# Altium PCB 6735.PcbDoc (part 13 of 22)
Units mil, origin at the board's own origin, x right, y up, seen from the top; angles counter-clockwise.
Board outline 2641.73 x 5165.35 mil, 6 copper layers (Top, Inner Layer 2, Inner Layer 3, Inner Layer 4, Inner Layer 5, Bottom), stack 35.7 mil thick; 1011 components, 790 nets, 4118 pads, 9325 vias.
Unrouted connection lines stored in the file: 4610.
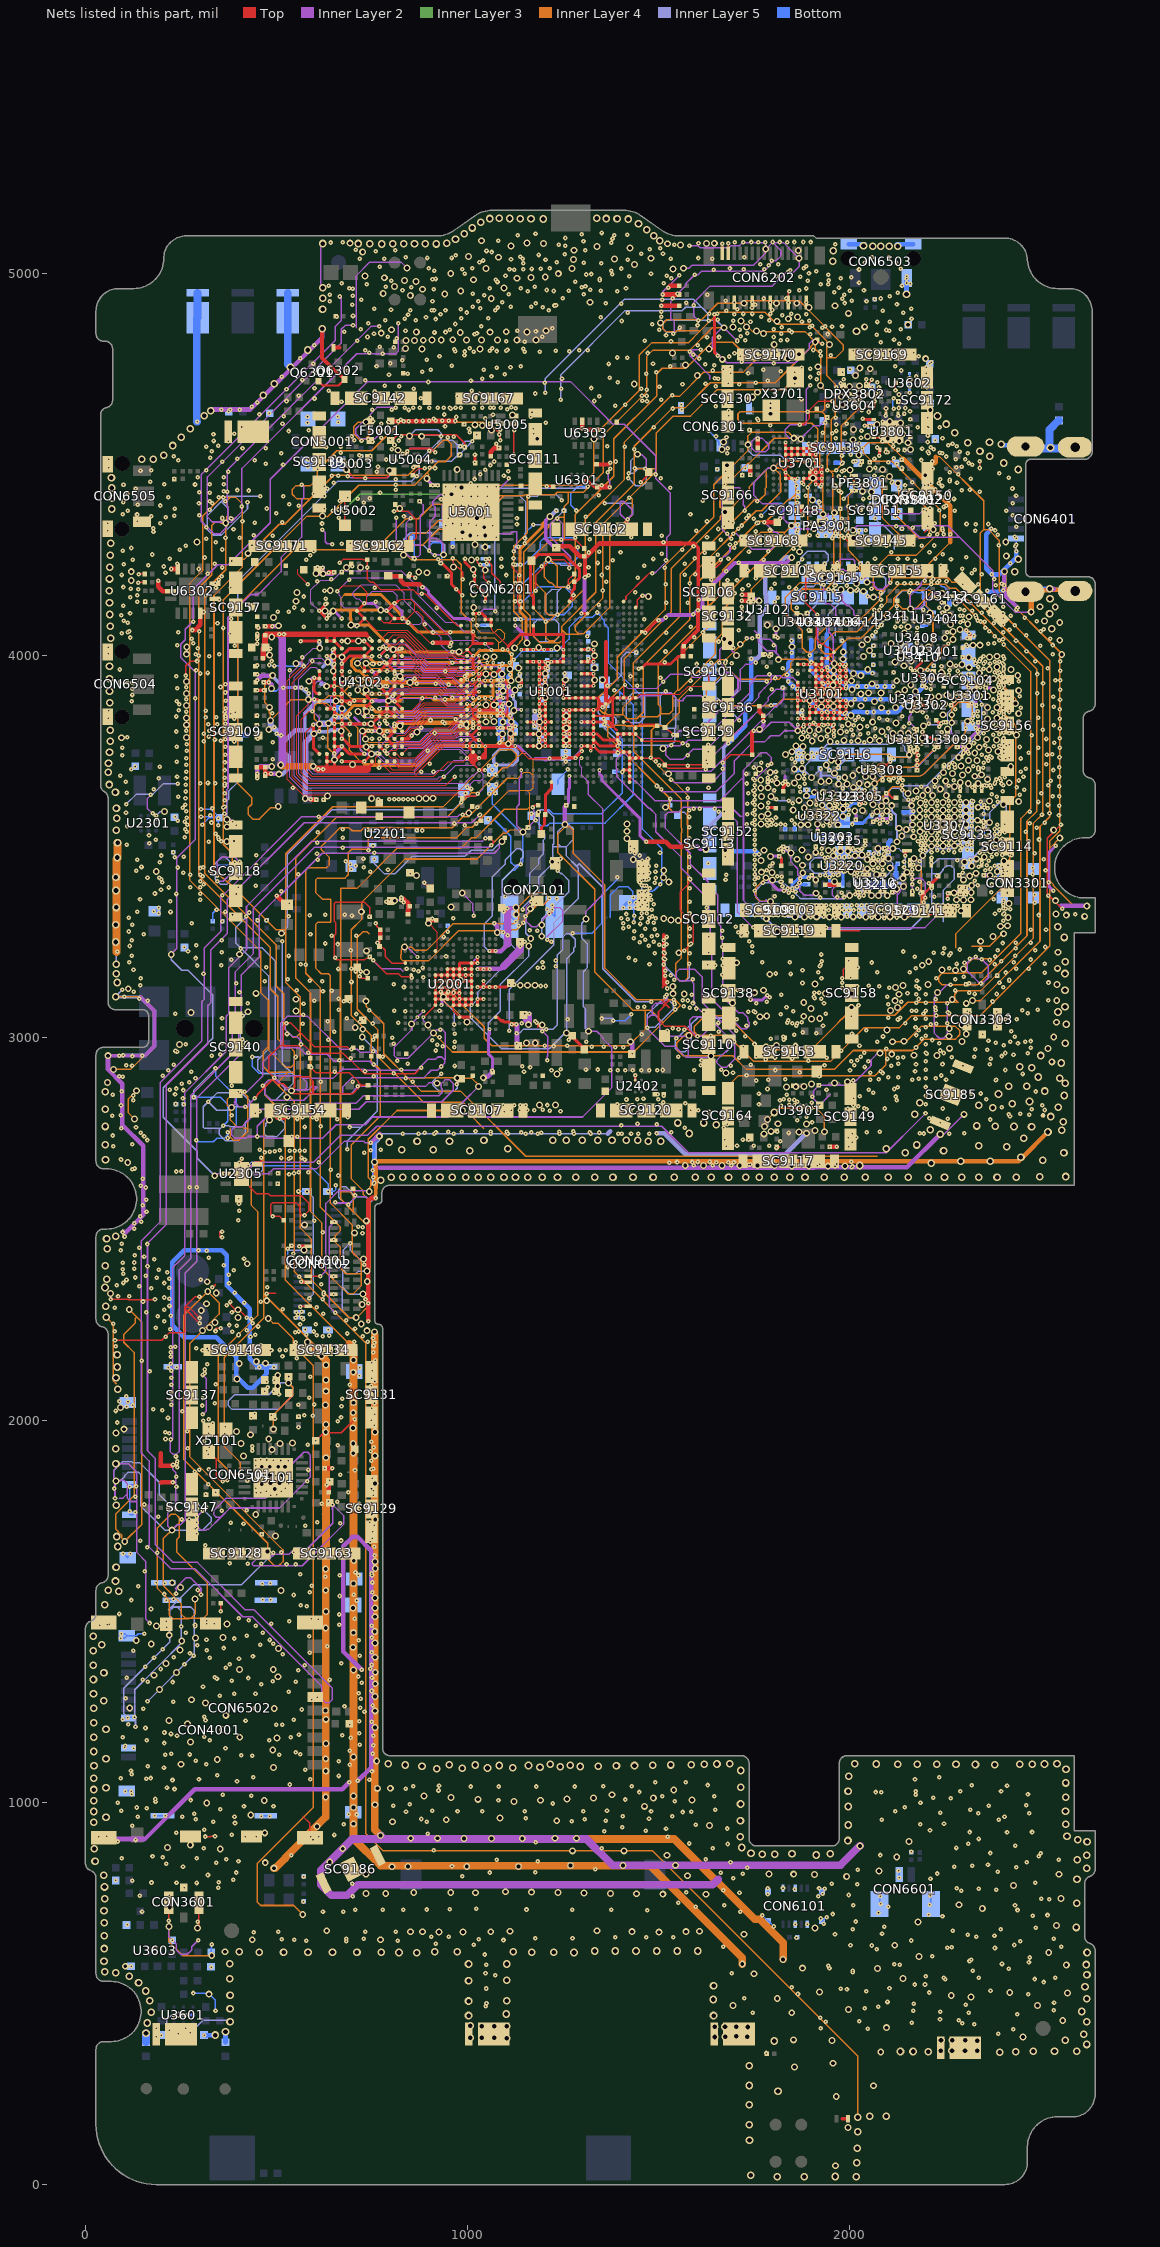
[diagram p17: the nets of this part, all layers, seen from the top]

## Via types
v1: diameter 12, hole 4, Top to Inner Layer 2, 3329 vias
v2: diameter 12, hole 4, Inner Layer 5 to Bottom, 3071 vias
v3: diameter 18, hole 10, Inner Layer 2 to Inner Layer 5, 1928 vias
v4: diameter 10, hole 4, Top to Inner Layer 2, 525 vias
v5: diameter 20, hole 12, Top to Bottom, 472 vias

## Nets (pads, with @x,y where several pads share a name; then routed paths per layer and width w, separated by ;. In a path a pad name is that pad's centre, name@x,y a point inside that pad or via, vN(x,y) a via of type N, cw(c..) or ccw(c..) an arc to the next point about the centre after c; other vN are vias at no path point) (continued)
D_GND: (continued)
  other v3: 1962.31,49.09 1995.15,148.83 1964.31,230.54 2061.64,258.45 1854.82,307.71 1956.17,317.5 2080.63,346.62 1953.05,376.92 1852.87,378.64 2453.27,386.18 2095.55,410.38 2556.8,429.38 246.3,444.09 1847.87,449.5 1996,458.39 1694,468.72 2490.77,468.68 1809.98,487.02 2316.68,490.42 2265.13,494.49 323.3,498.09 2569.01,501.28 2418.42,502.63 1920.87,504.09 2138.96,539.26 1748.85,551.39 2072.49,565.04 1876.41,566.08 104.31,571.09 2566.29,574.53 2181.02,596.24 2520.17,607.09 365.31,609.09 2117.26,626.08 436.42,640.39 771.95,640.49 1723.4,654.7 1500.37,660.31 850.6,661.48 881.79,661.48 924.87,661.07 987.81,660.67 1060.28,661.48 1430.36,661.57 1571.01,661.57 1110.79,662.67 1606.81,662.84 631.31,664.09 1338.21,663.86 293.31,671.09 1908.34,671.27 2540.52,677.63 2178.31,687.13 2346.52,722.4 220.31,725.09 2285.48,731.9 2552.73,748.18 1623.29,759.55 1510.6,759.67 1441.96,760.72 733.89,761.78 785.63,761.78 1373.32,761.78 1020.6,763.36 1304.68,762.83 859.03,764.42 955.66,763.89 1236.03,763.89 1167.39,764.95 1098.75,766 2427.92,782.09 1991.62,805.88 1574.9,807.94 1907.72,811.25 733.89,811.94 1788.47,812.35 1852.98,812.06 2547.3,811.94 2076.14,820.29 801.78,831.59 843.84,832.03 997.62,832.23 1132.59,831.92 1269.37,834.62 1406.49,835 1543.61,835.38 470.41,842.12 639.29,843.77 2122.48,857.23 1521.28,861.56 352.78,878.19 673.22,878.65 214.59,882.23 274.39,888.69 2154.41,897.92 1062.03,905.56 1142.89,905.23 851,906.05 920.76,905.89 990.52,905.73 1228.38,905.89 1284.82,905.89 469.15,920.21 605.79,936.54 1632.56,939.16 701.02,943.96 803.34,949.24 1233.08,951.76 943.86,954.28 1085,959.32 432.52,967.2 701.1,986.7 1462.44,989.57 757.83,993.54 317.22,998.6 1120.92,1002.17 467.89,1004.93 1190.23,1005.32 1587.2,1005.95 1027.03,1007.84 1259.54,1008.47 956.46,1012.25 1328.85,1011.62 1485.75,1011.62 628.83,1014.07 700.88,1016.52 885.89,1016.66 1377.37,1019.81 1539.31,1032.41 763.94,1036.68 797.67,1036.82 628.85,1082.17 491.78,1091.54 250.3,1099.72 761.9,1108.25 344.73,1112.01 628.58,1114.07 700.98,1118.26 489.98,1136.87 629.22,1153.68 274.62,1157.73 501.09,1168.29 403.78,1170.37 358.96,1190.24 757.95,1195.47 267.35,1205.7 218.63,1214.37 629.29,1217.14 367.24,1227.63 757.83,1239.41 628.33,1240 494.08,1245.7 115.73,1247.09 313.99,1259.63 277.62,1268.52 757.71,1277.1 193.56,1295.22 758.07,1310.23 503.84,1328.42 179.07,1332.35 238.11,1339.68 758.19,1340.36 701.04,1346.53 402.65,1347.74 491.35,1347.69 210.96,1363.51 757.83,1379.49 247.34,1398.7 504.95,1402.37 700.34,1405.64 172.13,1413.94 757.35,1416.94 132.74,1423.26 288.07,1430.11 359.51,1431.21 219.11,1437.36 701.19,1443.87 756.75,1446.95 628.82,1456.37 186.1,1460.95 370.56,1466.51 757.29,1485.62 629.37,1499.04 700.21,1508.26 757.6,1508.16 757.6,1534.85 511.66,1554.64 628.64,1554.86 248.46,1562.01 227.06,1574.49 628.55,1610.68 758.27,1612.1 757.44,1630.17 701.91,1632.29 475.91,1656.02 497.06,1697.23 758.19,1740.24 445.56,1753.15 495.31,1820.09 461.31,1832.09 757.67,1834.1 484.31,1835.09 507.31,1835.09 462.31,1856.09 482.31,1856.09 515.31,1856.09 461.31,1878.09 482.31,1878.09 504.31,1878.09 522.31,1878.09 629.12,1901.46 413.67,1906.42 757.24,1906.58 700.5,1913.29 487.66,1922.68 407.17,1938.94 508.8,1938.94 700.64,1939.16 541.45,1940.02 479.7,1950.81 431.75,1961.6 80.31,1966.09 757.37,1968.52 628.64,1968.94 395.48,1970.59 100.92,1976.32 700.37,1979.21 629.14,1988.85 700.58,2019.32 91.35,2032.95 628.39,2039.65 700.92,2045.61 629.08,2075.7 756.46,2075.78 628.99,2104.65 396.6,2107.25 502.95,2117.49 700.81,2125.22 629.04,2144.51 402.29,2147.91 471.4,2148.72 447.01,2153.6 701.01,2157.59 617.78,2167.27 426.79,2180.83 756.53,2231.03 736.7,2234.01 306.33,2234.83 324.45,2242.53 721.67,2251.7 339.32,2255.25 399.42,2268.53 303.06,2286.65 399.42,2288.62 724,2302.25 316.89,2304.44 474.29,2312.55 342.23,2332.72 318.49,2362.04 423.31,2409.05 704.28,2490.05 572.81,2510.97 1892.32,2664.2 1942.72,2664.44 1847.75,2665.28 1987.05,2664.99 1569.14,2666.29 1617.38,2666.36 1665.62,2666.43 1711.93,2666.4 1758.25,2666.38 1803.18,2666.35 110.49,2673.65 756.36,2675.06 1775.12,2749.02 1866.62,2753.85 1793.31,2755.56 1908.74,2758.07 1776.97,2768.01 1886.31,2774.56 1811.92,2775.3 1430.61,2820.16 1406.41,2820.72 1454,2820.79 1187.54,2824.22 1229.46,2824.68 527.72,2844.66 1834.23,2871.17 1858.55,2872.38 1879.59,2872.55 1899.43,2879.31 1960.15,2882.44 57.77,2883.63 1993.71,2885.16 1233.31,2905.83 1676.16,2908.06 2528.38,2937.47 2168.12,2954.59 2227.72,2954.32 2109.7,2957.43 2518.31,2972.09 2260.93,2972.76 1780.49,2976.87 1808.26,2980.13 245.63,2983.06 1153.95,2986.83 1176.95,2986.83 2293.69,2990.2 2141.65,2991.27 2533.31,3002.09 2259.51,3004.39 1578.97,3006.21 2304.31,3010.09 2096.98,3020.33 725.36,3022.77 2260.12,3024.32 705.81,3027.11 2292.87,3033.5 1194.95,3033.83 2540.31,3041.09 1899.9,3049.39 1921.08,3050.58 1764.5,3055.46 1879.31,3056.56 1782.59,3057.72 276.01,3066.42 550.74,3070.25 2106.58,3071.62 1898.31,3076.56 2004.15,3080.09 2124.67,3079.96 2304.52,3090.52 1879.31,3092.56 2118.05,3097.39 2541.31,3098.09 2267.91,3100.26 550.47,3101.12 1692.85,3110.12 1566.78,3114.57 2128.14,3114.14 1537.34,3115.7 446.59,3116.68 1936.15,3116.59 2004.15,3116.59 2229.6,3119.22 1774.3,3124.85 111.89,3128.63 2119.16,3131.5 968.95,3133.83 1536.76,3134.17 2139.31,3137.09 1137.53,3137.76 1156.87,3137.78 1175.95,3137.83 2204.18,3140.13 2542.31,3140.09 1909.15,3141 981.83,3150.49 1790.31,3166.56 734.95,3171.83 2276.31,3177.09 2241.31,3178.09 2297.68,3180.64 2543.31,3182.09 2189.31,3190.09 1704.09,3196.53 2206.31,3200.09 402.75,3218.89 1552.29,3222.91 2544.31,3224.09 734.95,3227.83 2342.21,3252.99 2374.57,3265.51 1810.65,3278.09 2393.87,3291.99 2412.19,3293.3 1550.95,3306.83 1531.95,3308.83 1512.95,3312.09 2414.15,3315.28 1856.64,3316.75 1881.22,3316.75 1946.86,3316.69 1977.5,3316.75 2008.88,3316.78 2041.55,3316.7 2073.67,3316.67 2105.24,3316.78 2614.31,3318.09 2566.31,3321.09 1126.88,3322.53 1829.65,3323.59 2539.31,3324.09 721.73,3330.13 2290.65,3332.59 1163.95,3337.83 956.7,3342.85 2416.4,3351.68 2538.31,3359.09 2278.65,3361.59 2297.65,3360.59 2316.65,3361.59 2056.65,3372.59 2097.65,3372.59 2272.65,3379.59 2317.65,3380.59 2318.65,3398.59 1526.28,3408.14 1797.46,3412.75 2138.65,3417.59 1512.07,3419.84 2313.65,3423.59 866.29,3425.11 2330.22,3430.75 1768.65,3433.59 1796.65,3432.59 2149.84,3433.47 185.07,3435.36 2385.65,3435.59 1512.93,3437.82 2104.65,3444.59 2318.65,3449.59 1875.65,3451.59 2299.65,3460.59 2402.93,3462.6 1767.65,3464.59 1433.33,3466.97 1861.65,3467.59 2045.65,3466.59 2100.65,3469.59 2167.65,3469.59 2331.65,3468.59 1891.18,3473.16 2351.65,3473.59 1956.65,3476.59 2013.65,3476.59 2190.65,3477.59 2031.65,3478.59 2367.65,3488.59 1674.05,3490.92 1775.6,3491 1874.65,3491.59 1943.65,3490.59 2213.65,3501.59 2243.7,3502.1 2273.66,3502.57 2367.65,3508.59 2383.65,3518.59 2213.65,3520.59 2243.65,3520.59 2273.65,3520.59 2303.65,3520.59 1416.49,3521.83 2166.88,3526.19 1144.95,3538.83 2183.65,3539.59 2213.65,3539.59 2243.65,3539.59 2273.65,3539.59 2303.65,3539.59 1416.5,3540.84 2533.18,3543.66 2147.65,3545.59 2335.65,3546.59 2128.65,3548.59 370.31,3552.41 1871.65,3557.59 1890.65,3557.59 1968.65,3557.59 2163.65,3557.59 1767.65,3559.59 2183.65,3558.59 2213.65,3558.59 2243.65,3558.59 2273.65,3558.59 2303.65,3558.59 1417.04,3559.64 1939.65,3567.59 2333.65,3569.59 2164.67,3576.56 2182.65,3577.59 2213.65,3577.59 2243.65,3577.59 2273.65,3577.59 2303.65,3577.59 1768.65,3579.59 1879.65,3578.59 1981.65,3579.59 1785.65,3586.59 1002.75,3588.3 1919.65,3591.59 2012.65,3593.59 2070.65,3592.59 2096.65,3593.59 2032.65,3594.59 1851.65,3596.59 2182.65,3596.59 2213.65,3596.59 2243.65,3596.59 2273.65,3596.59 2303.65,3596.59 1981.65,3598.59 1880.65,3601.59 1517.32,3603.57 2335.65,3603.59 1767.65,3606.59 1946.65,3607.59 2082.65,3606.59 2161.65,3607.59 1927.65,3608.59 2401.65,3610.59 1895.65,3614.59 2184.65,3614.59 2213.65,3615.59 2243.65,3615.59 2273.65,3615.59 2303.65,3615.59 1981.65,3617.59 2365.65,3619.59 2441.65,3618.59 1866.65,3621.59 748.83,3626.09 1768.65,3631.59 1793.65,3631.59 2035.65,3631.59 2190.65,3634.59 2216.65,3634.59 2252.32,3634.61 1981.65,3636.59 2004.65,3637.59 1954.65,3639.59 1929.65,3641.59 1906.65,3642.59 2172.65,3645.59 2236.65,3651.59 1766.65,3653.59 2009.65,3655.59 2273.65,3657.59 2045.65,3662.59 1992.65,3664.59 2309.65,3665.59 2335.65,3665.59 1809.65,3666.59 1855.14,3667.2 2417.08,3667.58 2222.45,3672.57 1945.65,3672.59 2250.65,3672.59 1766.65,3674.59 2359.65,3676.59 1986.65,3681.59 1865.65,3682.59 2040.65,3683.59 2326.65,3684.59 2007.65,3686.59 2294.65,3687.59 2344.23,3688.48 2268.65,3691.59 1959.65,3692.59 1791.65,3694.59 2244.65,3694.59 2309.65,3700.59 1763.65,3703.59 1854.65,3703.59 1874.65,3704.59 2420.74,3710.35 2290.65,3711.59 1969.65,3721.59 2310.65,3725.59 2332.65,3725.59 1951.48,3726.51 2284.65,3733.59 1889.65,3734.59 1831.65,3741.59 2326.65,3745.59 1848.65,3748.59 2387.65,3749.59 2362.65,3753.59 1511.31,3757.09 2338.56,3760.5 1858.65,3763.59 1877.65,3762.59 2173.65,3771.59 1948.65,3775.59 1901.65,3776.59 2021.65,3777.59 2077.65,3777.59 2103.65,3776.59 1257.95,3779.49 1984.65,3778.59 2052.65,3779.59 2383.65,3779.59 2357.65,3780.59 1924.65,3783.59 93.95,3785.36 1874.65,3784.59 2189.65,3784.59 264.31,3786.25 2170.65,3790.59 2436.22,3792.77 2112.65,3796.59 2132.65,3796.59 2152.65,3796.59 1975.65,3800.59 2083.65,3801.59 1942.65,3804.59 2358.65,3809.59 2384.65,3808.59 2026.65,3813.59 2192.76,3815.79 264.31,3819.11 1995.65,3821.59 2120.65,3823.59 2059.65,3826.59 2359.65,3834.59 264.31,3837.29 2384.65,3836.59 1257.95,3842.49 2002.65,3843.59 2243.65,3845.59 2441.65,3848.59 2175.65,3858.59 2082.64,3863.68 2119.37,3864.71 2359.65,3864.59 2384.65,3864.59 1926.11,3866.37 1957.4,3866.73 2226.65,3867.59 2028.97,3869.08 264.31,3870.04 2247.65,3873.59 2002.65,3874.59 2064.65,3880.59 1895.08,3882.14 1925.79,3885.09 1957.21,3885.49 2271.65,3885.59 2168.65,3886.59 2212.65,3892.59 2232.65,3893.59 2359.65,3894.59 2253.76,3897.23 2028.65,3899.59 2126.34,3900.42 264.31,3901.49 1956.65,3903.59 2048.65,3902.59 2081.65,3902.59 2171.65,3906.59 2325.65,3909.59 2441.65,3908.59 2005.65,3911.59 2143.65,3910.59 1955.65,3922.59 2159.15,3923.59 2057.65,3926.59 264.31,3932.52 2004.65,3934.59 2122.65,3934.59 1332.31,3936.09 1132.95,3937.49 2355.65,3941.59 2375.65,3940.59 1957.67,3942.48 2028.65,3948.59 2439.15,3948.59 2009.15,3953.59 2338.65,3954.59 2239.65,3956.59 1957.65,3961.59 2046.65,3963.59 2364.65,3963.59 2421.65,3963.59 1132.95,3967.49 2311.65,3969.59 2384.65,3970.59 2141.65,3973.59 2293.65,3976.59 2261.65,3978.59 2117.65,3983.59 1981.65,3990.59 2035.56,3997.5 2365.65,3996.59 2384.65,3998.59 1332.08,4000.1 481.95,4001.49 2554.31,4003.09 264.49,4004.01 1982.75,4009.49 2051.25,4013.83 1185.95,4021.49 265.02,4022.86 1848.34,4023.34 2321.74,4027.47 2340.14,4027.52 2031.65,4028.59 1713.15,4030.09 1332.08,4031.1 2107.65,4031.59 2132.37,4032.51 1686.31,4033.09 2548.95,4040.49 2046.35,4042.56 2269.65,4042.59 1671.31,4044.09 2248.23,4046.67 487.32,4049.01 2142.65,4059.59 2288.25,4068.84 2151.81,4075.65 1783.65,4080.59 2262.88,4081.46 2308.45,4082.54 2548.95,4086.49 2509.31,4091.09 2086.56,4097.5 491.81,4100.2 2311.45,4102.04 1871.21,4103.01 2260.76,4105.98 2132.56,4109.5 2209.99,4112.06 626.97,4117.22 2253.65,4125.59 2537.31,4127.09 2497.31,4128.09 2277.04,4138.35 550.95,4142.49 1015.17,4161.78 1045.95,4161.77 553.31,4165.22 2035.65,4168.59 640.51,4170.26 2001.65,4171.09 1013.03,4187.47 2017.65,4188.59 119.95,4196.83 893.31,4217.09 871.95,4218.83 119.95,4219.83 1045.95,4223.99 1014.71,4225.6 683.31,4231.09 719.31,4231.09 962.87,4232.12 1010.04,4250.53 2409.31,4261.09 424.95,4267.83 1868.31,4272.09 1045.81,4284.38 1019.31,4291.09 291.95,4297.83 2407.95,4297.83 2009.51,4308.35 1006.78,4314.38 1045.76,4314.17 986.47,4323.17 1378.79,4323.46 2218.18,4329.89 1024.08,4359.98 1037.92,4378.07 2054.31,4391.09 1902.31,4407.09 2056.31,4428.09 2033.31,4430.09 2103.31,4469.09 2197.31,4472.09 2000.31,4486.09 682.23,4487.48 972.56,4487.5 2085.31,4487.09 2051.31,4488.09 1678.31,4498.51 2023.18,4524.89 817.86,4537.63 1665.31,4539.54 2158.31,4539.09 2152.31,4557.09 1668.95,4558.83 2129.31,4562.09 2008.31,4565.09 1330.23,4566.55 2099.31,4568.09 2046.18,4573.89 2137.31,4580.09 2067.18,4582.39 2009.31,4592.09 2090.31,4593.09 1038.31,4602.09 1019.31,4604.09 2071.31,4605.09 2132.31,4609.09 2104.31,4613.09 1117.31,4630.09 2210.3,4643.09 1980.92,4656.4 1745.28,4677.06 1977.33,4677.37 1994.31,4685.09 2024.31,4686.09 1758.62,4689.17 1999.31,4704.09 2025.31,4706.09 1435.7,4710.61 2156.3,4723.09 1600.85,4733.21 2014.31,4733.09 2053.24,4750.72 2026,4753.03 1916.31,4756.09 1569.67,4760.41 1666.28,4775.42 1837.98,4777.43 2198.3,4777.09 1867.29,4788.93 1535.54,4791.8 880.85,4802.49 1631.53,4802.19 837.66,4803.53 1032.55,4802.83 1946.52,4814.02 838.68,4824.37 860.93,4824.83 883.64,4825.3 906.81,4825.76 930.91,4826.22 997.19,4826.22 1036.35,4825.73 1078.18,4825.73 1128.6,4825.73 1179.02,4825.73 961.04,4826.69 1773.95,4842.63 773.95,4843.83 980.59,4845.76 1058.57,4846.45 865.65,4846.72 1155.09,4847.26 1101.01,4847.67 1755.33,4849.31 1205.08,4850.32 800.95,4852.83 1693.96,4859.59 1729.13,4859.98 2038.75,4860.49 2152.3,4866.09 1504.82,4870.95 1809.31,4875.09 1838.95,4881.49 1863.04,4886.07 1996.53,4895.76 1892.95,4910.83 1961.4,4915.57 1808.31,4922.09 1860.93,4922.09 1320.19,4924.78 1061.54,4934.58 849.95,4942.83 939.95,4946.57 778.95,4947.83 982.03,4954.47 881.95,4958.83 1095.23,4961.85 808.95,4965.83 864.95,4978.83 834.95,4981.83 1014.91,4983.77 1129.31,4987.51 781.95,4988.83 1165.81,4989.12 1203.1,4990.72 731.29,4993.4 1237.19,4999.54 955.8,4999.76 1536.95,5011.83 1047.78,5013.07 1273.28,5012.78 1436.75,5023.75 1277.29,5036.44 1384.09,5037.79 1479.79,5039.88 1080.66,5042.38 1002.02,5044.82 725.28,5056.02 1864.95,5059.83 1278.09,5060.9 1424.46,5067.05 1338.45,5070.56 1113.54,5071.68 1556.95,5074.83 1198.61,5078.17 1522.95,5077.83 692.49,5079.33 1624.95,5078.83 1645.31,5079.09 1155.32,5079.92 1036.54,5085.77
  other v4: 1886.43,2793.19 1854.93,2824.69 1057.32,3022.72 1250.45,3858.25 1092.97,3889.74 1250.45,3889.74 1077.22,3921.24
  other v5: 1880.26,20.09 2016.73,20.13 1809.78,20.71 1961.96,20.93 1740.28,24.18 2018.31,57.09 2019.31,95.09 1737.3,116.09 2020.31,138.09 1736.3,156.09 2052.31,179.09 2095.31,179.09 1736.3,209.09 1811.95,244.49 1736.3,259.09 1736.3,311.09 2392.31,346.09 2205.31,347.09 2434.31,347.09 2132.31,348.09 2165.31,348.09 2479.31,349.09 2535.31,349.09 2593.31,349.09 2237.66,349.74 2267.12,349.74 2301.3,350.09 2333.3,350.09 2619.72,366.56 1801.95,375.49 2333.3,376.09 2238.3,377.09 2268.3,377.09 2302.3,377.09 2563.3,377.09 1102.3,383.09 1006.3,384.09 1037.3,384.09 1069.3,384.09 1646.3,386.09 1674.3,387.09 1731.3,387.09 1702.3,388.09 2611.56,392.85 1732.3,412.09 1646.3,413.09 1673.3,413.09 1702.3,413.09 1037.3,414.09 1069.3,414.09 1102.3,414.09 1006.3,415.09 161.85,422.68 2619.9,425.7 1002.3,442.09 1643.3,442.09 1101.3,446.09 172.52,450.64 2606.9,452.77 378.3,460.09 1002.3,480.09 167.84,481.31 1102.3,481.09 1642.3,484.09 2619.6,485.77 378.3,495.09 157.97,506.28 2615.14,517.61 1643.3,520.09 138.93,527.83 1002.3,533.09 1102.3,534.09 377.3,538.09 114.4,544.82 2620.21,548.89 79.63,554.1 50.24,556.48 2618.54,575.54 1002.3,577.09 1102.3,577.09 377.3,578.09 48.59,583.78 866.31,606.09 820.31,607.09 1278.3,607.09 2620.51,607.13 454.31,608.09 518.31,608.09 582.31,608.09 646.31,608.09 710.31,608.09 774.31,608.09 1167.3,608.09 1225.3,608.09 402.31,609.09 914.31,609.09 972.3,609.09 1119.3,609.09 1332.31,611.09 1386.31,611.09 1440.31,611.09 1494.31,611.09 1548.31,611.09 1602.31,611.09 48.83,617.43 49.06,651.08 2592.16,672.69 49.29,684.49 48.48,716.31 2593.68,736.11 50.65,748.13 49.84,778.59 2594.29,798.62 47.39,809.05 2619.3,827.58 25.09,846.04 2594.81,849.74 1912.39,862.21 2619.9,861.73 1770.4,864.21 1803.31,864.07 1848.59,865.59 1948.43,865.7 1741.27,866.73 23.45,878.67 1716.75,881.89 2620.51,896.8 1994.92,899.95 2595.83,901.87 1712.86,910.06 2568.07,911.29 1995.89,940.61 2564.93,942.69 21.33,947.51 1713.67,951.9 53.79,961.07 21.58,976.01 2564.18,976.37 1995.57,989.02 1713.93,995.73 21.83,1004.52 2564.44,1013.29 1995.25,1029.03 21.95,1033.4 53.79,1037.76 1714.2,1039.56 2564.95,1050.73 21.95,1062.9 1996.86,1068.4 1714.47,1083.39 2565.46,1086.63 919.11,1088.2 985.93,1089 1051.94,1089.8 1117.95,1090.6 1189.31,1091.67 1241.96,1092.74 880.49,1094.14 1294.61,1093.81 22.24,1095.43 1341.91,1094.61 1389.22,1095.41 1082.19,1096.46 1159.24,1096.46 1436.52,1096.22 1268.11,1096.86 1483.83,1097.02 837.12,1097.63 951.72,1098.01 1020.25,1097.63 1531.13,1097.82 1585.38,1098.62 1618.79,1099.42 2226.97,1099.45 2277.74,1099.2 2328.52,1098.94 2379.29,1098.68 2444.17,1099.2 1216.15,1099.95 1652.2,1100.22 2013.11,1100.48 2069.27,1100.22 2125.42,1099.97 2176.2,1099.71 2476.74,1099.71 2509.3,1100.22 792.6,1101.11 1685.61,1101.03 2541.87,1100.74 53.79,1114.45 22.02,1133.08 21.79,1170.74 53.79,1191.14 21.57,1208.39 21.35,1246.04 47.98,1265.89 21.13,1283.7 20.91,1321.35 48.37,1339.48 20.69,1359.01 20.47,1396.66 42.17,1412.69 20.17,1434.2 50.56,1516.8 87.37,1552.01 59.34,1555.25 78.69,1578.96 80.03,1614.91 84.79,1669.4 81.76,1695.34 80.28,1776.94 79.72,1885.45 79.56,1925.56 84.53,2080.6 79.85,2110.74 83.1,2139.06 82.67,2171.1 53.29,2298.08 51.12,2346.89 55.68,2368.31 52.05,2404.02 57.01,2448.21 55.23,2474.99 79.5,2481.06 773,2627.73 800.06,2635 830.06,2635 862.56,2635 895.06,2635 927.56,2635 960.06,2635 995.06,2635 1027.56,2635 1060.06,2635 1095.06,2635 1125.06,2635 1157.56,2635 1195.06,2635 1235.06,2635 1282.56,2635 1332.56,2635 1380.06,2635 1432.56,2635 1485.06,2635 1540.06,2635 1595.06,2635 1637.56,2635 1682.56,2635 1727.56,2635 1762.56,2635 1802.56,2635 1842.56,2635 1882.56,2635 1932.56,2635 1985.06,2635 2040.06,2635 2100.06,2635 2152.56,2635 2205.06,2635 2247.56,2635 2292.56,2635 2337.56,2635 2385.06,2635 2435.06,2635 2497,2636.68 2565.07,2637.23 2025.62,2666.15 2212.56,2672.5 2290.06,2677.5 2367.56,2677.5 2505.06,2680 52.48,2681.18 2447.56,2687.5 2145.06,2700 2560.06,2700 1005.06,2705 2245.06,2705 827.56,2707.5 910.06,2707.5 1105.06,2710 2095.06,2710 2410.06,2715 2337.56,2717.5 2175.06,2720 51.91,2720.92 795.06,2727.5 867.56,2730 952.56,2730 1472.56,2730 1505.06,2730 1042.56,2732.5 1222.56,2732.5 1257.56,2732.5 1300.06,2732.5 1340.06,2732.5 1377.56,2732.5 1415.06,2732.5 1445.06,2732.5 2455.06,2737.5 1580.06,2750 2553.96,2758.4 2210.06,2760 2475.33,2767.42 51.91,2768.4 2429.47,2768.17 2380.61,2768.92 2331.75,2769.67 1650.06,2772.5 1550.06,2777.5 1617.56,2777.5 2558.02,2780.2 2525.5,2794.25 2170.06,2800 1802.56,2805 51.91,2813.69 2373.74,2817.04 2545.24,2818.54 2337.61,2824.27 2424.88,2827.61 2182.56,2830 2469.91,2833.72 2561.03,2849.36 2388.75,2853.18 51.91,2858.98 2509.94,2860.96 2415.99,2873.19 2462.69,2873.19 2563.62,2881.35 2548.85,2894.87 2492.7,2897.65 2476.03,2921.55 2444.34,2924.89 2552.75,2934.28 2499.37,2953.8 2563.3,2986.04 2566.08,3036.07 2544.46,3067.9 2562.75,3081.1 2562.75,3125.01 82.76,3145 80.25,3168.32 2562.75,3168.37 2563.86,3199.5 79.55,3251 2561.08,3262.88 2543.73,3290.58 79.27,3296.4 80.14,3341.39 79.96,3385.74 79.76,3420.42 82.95,3472.07 80.56,3543.43 81.92,3574.26 81.08,3601.2 78.42,3642.48 61.95,3662.83 59.86,3694.72 60.31,3718.83 62.95,3747.83 64.95,3775.83 64.95,3804.83 63.95,3876.83 62.95,3906.83 62.95,3939.83 62.95,3972.83 65.95,4045.83 2528.61,4070.87 64.95,4076.83 63.95,4107.83 2522.43,4109.44 62.95,4138.83 2523.67,4149.25 61.95,4169.83 62.95,4200.83 2430.96,4219.76 63.95,4231.83 2440.35,4252.06 64.95,4262.83 65.95,4293.83 68.95,4383.83 69.95,4411.83 68.95,4438.83 67.95,4465.83 2440.31,4487.09 2402.31,4504.09 146.95,4513.83 176.95,4513.83 2366.31,4522.09 204.95,4524.83 2340.31,4535.09 2524.81,4544.11 227.95,4549.83 2308.3,4557.09 2365.3,4558.09 250.95,4571.83 2274.3,4583.09 273.95,4593.83 2252.3,4606.09 2229.3,4627.09 310.95,4627.83 464.87,4681.77 493.53,4711.87 581.53,4799.87 2017.31,4849.09 620.31,4906.09 620.65,4935.59 1955.57,5032.32 1956.89,5059.15 2081.16,5071.58 2103.35,5071.51 2059.57,5071.73 775.39,5077.07 860.9,5077.56 889.36,5077.44 917.83,5077.31 713.51,5078.3 744.08,5077.69 803.98,5077.81 832.44,5077.69 945.05,5079.54 1502.66,5085.33 968.19,5089.69 1486.83,5098.88 991.03,5104.43 1468.18,5114.72 1012.31,5119.19 1446.87,5130.36 1034.36,5134.4 1198.19,5142.48 1420.12,5142.38 1137.63,5143.41 1165.58,5142.94 1390.87,5143.06 1057.81,5143.72 1082.19,5144.34 1109.68,5143.88 1337.6,5144.42 1362.54,5143.74
DISP_PWM0: U1001.AH31 U2305.5 | length 3822.8
  Top w4: v1(363.73,2644.46) U2305.5@366.61,2644.49 ; U1001.AH31@1407.93,4141.71 1414.25,4148.03 1414.25,4154.9 1464.72,4205.37 1474.57,4215.22 v1(1482.98,4215.22)
  Inner Layer 2 w4: v3(224.31,3218.19) 224.31,3219.36 239.31,3234.36 239.31,3471.14 287.31,3519.14 287.31,3957.11 249.31,3995.11 249.31,4029.86 260.89,4041.44 260.89,4068.94 282.08,4090.13 282.08,4173.56 346.35,4237.83 373.14,4237.83 483.31,4348 483.31,4461.79 738.61,4717.09 1268.94,4717.09 1380.3,4605.73 1409.58,4605.73 1492.31,4523 1492.31,4463.51 1530.31,4425.51 1530.31,4318.41 1520.31,4308.41 1520.31,4246.56 1491.45,4217.7 1485.46,4217.7 v1(1482.98,4215.22) ; v3(338.31,2639.27) 343.5,2644.46 v1(363.73,2644.46)
  Inner Layer 5 w4: v3(224.31,3218.19) 224.31,3204.62 251.84,3177.09 268.22,3177.09 332.78,3112.53 332.78,2999.35 203.31,2869.88 203.31,2792.34 292.31,2703.34 292.31,2685.27 v3(338.31,2639.27)
DQ0: U1001.A12 U4102.W12 | length 200.5
  Top w3: U4102.W12@808.67,3782.47 818.5,3792.31 835.03,3792.31 853.33,3810.61 862.33,3810.61 896.15,3844.43 972.61,3844.43 974.54,3842.5 U1001.A12@982.73,3842.5
DQ1: U1001.C10 U4102.V11 | length 250.5
  Inner Layer 2 w3: v1(788.98,3802.15) 815.02,3776.11 875.08,3776.11 896.08,3797.11 965.83,3797.11 970.33,3801.61 1004.84,3801.61 v4(1014.23,3811)
DQ2: U1001.B12 U4102.V13 | length 195
  Top w3: U4102.V13@828.35,3802.16 828.55,3802.36 836.08,3802.36 850.33,3816.61 859.33,3816.61 894.64,3851.92 988.22,3851.92 998.06,3842.08 U1001.B12@998.48,3842.5
DQ3: U1001.C11 U4102.U11 | length 258
  Inner Layer 2 w3: v1(788.98,3821.84) 813.71,3797.11 835.08,3797.11 851.58,3813.61 873.58,3813.61 878.08,3809.11 959.83,3809.11 985.33,3834.61 1006.37,3834.61 v4(1014.23,3826.75)
DQ4: U1001.B13 U4102.U13 | length 185.2
  Top w3: U4102.U13@828.35,3821.84 832.12,3825.61 859.33,3825.61 891.97,3858.24 U1001.B13@998.48,3858.25
DQ5: U1001.D12 U4102.T11 | length 250.1
  Inner Layer 2 w3: v1(788.98,3841.52) 815.43,3841.52 820.84,3836.11 865.33,3836.11 876.75,3847.53 1024.94,3847.53 v4(1029.98,3842.5)
DQ6: U1001.A14 U4102.T13 | length 167.8
  Top w3: U4102.T13@828.35,3841.53 831.93,3845.11 861.08,3845.11 887.46,3871.49 980.22,3871.49 U1001.A14@982.73,3873.99
DQ7: U1001.A15 U4102.R12 | length 194.3
  Top w3: U4102.R12@808.67,3861.21 818.51,3851.37 830.43,3851.37 830.69,3851.11 858.08,3851.11 884.46,3877.49 966.71,3877.49 978.96,3889.74 U1001.A15@982.73,3889.74
DQ8: U1001.B15 U4102.N12 | length 202.4
  Top w3: U4102.N12@808.67,3900.58 818.48,3910.39 842.79,3910.39 848.08,3905.11 967.33,3905.11 973.28,3899.16 989.06,3899.16 U1001.B15@998.48,3889.74
DQ9: U1001.B16 U4102.M13 | length 176.3
  Top w3: U4102.M13@828.35,3920.27 842.67,3920.26 851.83,3911.11 970.33,3911.11 975.97,3905.46 991.61,3905.46 ; 991.63,3905.49 U1001.B16@998.48,3905.49
DQ10: U1001.D15 U4102.M11 | length 253.6
  Inner Layer 2 w3: v1(788.98,3920.26) 795.14,3914.11 926.83,3914.11 938.83,3902.11 1017.61,3902.11 v4@1029.97,3889.74
  other v4: 1029.98,3889.74
DQ11: U1001.B17 U4102.L13 | length 191.9
  Top w3: U4102.L13@828.35,3939.95 835.51,3947.11 862.67,3947.11 874.67,3935.11 955.33,3935.11 978.97,3911.46 988.7,3911.46 U1001.B17@998.48,3921.24
DQ12: U1001.D17 U4102.L11 | length 267.1
  Inner Layer 2 w3: v1(788.98,3939.95) 799.82,3929.11 827.08,3929.11 842.08,3944.11 914.83,3944.11 944.83,3914.11 1022.85,3914.11 v4(1029.98,3921.24)
DQ13: U1001.C18 U4102.K11 | length 249.4
  Inner Layer 2 w3: v1(788.98,3959.63) 795.95,3966.61 874.33,3966.61 884.83,3956.11 932.83,3956.11 944.83,3944.11 959.83,3944.11 977.83,3926.11 1003.36,3926.11 v4(1014.23,3936.99)
DQ14: U1001.A17 U4102.K13 | length 173.6
  Top w3: U4102.K13@828.35,3959.64 832.32,3963.61 854.83,3963.61 877.33,3941.11 958.33,3941.11 978.2,3921.24 U1001.A17@982.73,3921.24
DQ15: U1001.A18 U4102.J12 | length 191.7
  Top w3: U4102.J12@808.67,3979.32 818.48,3969.5 830.93,3969.5 831.03,3969.61 857.83,3969.61 880.33,3947.11 961.33,3947.11 971.45,3936.98 U1001.A18@982.73,3936.99
DQ16: U1001.A9 U4102.AB12 | length 220.8
  Top w3: U4102.AB12@808.67,3723.42 808.66,3717.52 819.08,3707.11 855.58,3707.11 930.58,3782.11 964.33,3782.11 977.48,3795.25 U1001.A9@982.73,3795.25
DQ17: U1001.A8 U4102.AB11 | length 240.3
  Top w3: U4102.AB11@788.98,3723.42 788.98,3715.21 803.08,3701.11 858.58,3701.11 933.36,3775.89 979.11,3775.89 U1001.A8@982.73,3779.51
DQ18: U1001.B8 U4102.AB10 | length 276.2
  Top w3: U4102.AB10@769.3,3723.42 769.29,3722.91 797.1,3695.11 861.58,3695.11 936.32,3769.85 988.82,3769.85 U1001.B8@998.48,3779.51
DQ19: U1001.B11 U4102.AA13 | length 204.8
  Top w3: U4102.AA13@828.35,3743.1 846.36,3761.11 882.58,3761.11 921.58,3800.11 955.33,3800.11 972.16,3816.94 988.67,3816.94 U1001.B11@998.48,3826.75
DQ20: U1001.B10 U4102.AA12 | length 226.1
  Top w3: U4102.AA12@808.67,3743.1 814.09,3743.1 823.9,3733.28 863.76,3733.28 924.58,3794.11 958.33,3794.11 975.03,3810.81 998.28,3810.81 U1001.B10@998.48,3811
DQ21: U1001.C7 U4102.AA10 | length 320.5
  Top w3: v1(768.08,3707.11) 759.47,3715.72 759.47,3733.28 U4102.AA10@769.3,3743.1
  Inner Layer 2 w3: v1(768.08,3707.11) 777.08,3716.11 869.08,3716.11 913.78,3760.8 981.13,3760.8 981.26,3760.67 985.72,3756.22 989.83,3752.11 1002.58,3752.11 v4(1014.23,3763.76)
DQ22: U1001.A11 U4102.Y13 | length 180.9
  Top w3: U4102.Y13@828.35,3762.79 832.67,3767.11 879.58,3767.11 918.58,3806.11 952.33,3806.11 969.17,3822.94 978.93,3822.94 U1001.A11@982.73,3826.75
DQ23: U1001.D9 U4102.Y11 | length 254.5
  Inner Layer 2 w3: v1(788.98,3762.78) 790.3,3764.11 881.08,3764.11 902.08,3785.11 971.83,3785.11 976.33,3789.61 1024.34,3789.61 v4(1029.98,3795.25)
DQ24: U1001.D20 U4102.H11 | length 257.4
  Inner Layer 2 w3: v1(788.98,3999) 797.38,3990.61 886.33,3990.61 896.83,3980.11 944.83,3980.11 956.83,3968.11 989.08,3968.11 993.58,3972.61 1025.85,3972.61 v4(1029.98,3968.48)
DQ25: U1001.B19 U4102.H13 | length 189.3
  Top w3: U4102.H13@828.35,3999.01 833.75,3993.61 851.83,3993.61 886.33,3959.11 967.33,3959.11 973.7,3952.73 U1001.B19@998.48,3952.73
DQ26: U1001.D21 U4102.G10 | length 303.8
  Top w4: U1001.D21@1029.98,3984.23 v4(1029.98,3999.97)
  Inner Layer 2 w3: v1(769.29,4018.69) 782.46,4031.86 836.08,4031.86 865.33,4002.61 958.33,4002.61 970.33,3990.61 1008.77,3990.61 1009.9,3989.47 1019.48,3989.47 v4(1029.98,3999.97)
DQ27: U1001.A20 U4102.G12 | length 203
  Top w3: U4102.G12@808.67,4018.69 813.36,4018.69 823.18,4028.5 834.93,4028.5 892.33,3971.11 980.1,3971.11 U1001.A20@982.73,3968.48
DQ28: U1001.B20 U4102.G13 | length 198.7
  Top w3: U4102.G13@828.35,4018.69 835.75,4018.69 889.33,3965.11 970.33,3965.11 976.39,3959.05 989.04,3959.05 U1001.B20@998.48,3968.48
DQ29: U1001.B22 U4102.F10 | length 264.1
  Top w3: U4102.F10@769.3,4038.38 792.02,4061.11 838.33,4061.11 893.83,4005.61 968.83,4005.61 974.69,3999.74 998.25,3999.74 U1001.B22@998.48,3999.98
DQ30: U1001.B21 U4102.F11 | length 245.8
  Top w3: U4102.F11@788.98,4038.38 805.71,4055.11 835.33,4055.11 890.83,3999.61 965.83,3999.61 971.79,3993.65 984.81,3993.65 984.86,3993.61 989.1,3993.61 U1001.B21@998.48,3984.23
DQ31: U1001.A21 U4102.F12 | length 205.4
  Top w3: U4102.F12@808.67,4038.38 819.39,4049.11 832.33,4049.11 887.83,3993.61 962.83,3993.61 972.21,3984.23 U1001.A21@982.73,3984.23
DQM0: U1001.D14 U4102.R10 | length 281.7
  Inner Layer 2 w3: v1(769.29,3861.21) 775.19,3867.11 807.33,3867.11 826.33,3848.11 859.58,3848.11 872.96,3861.49 1017.48,3861.49 v4(1029.98,3873.99)
DQM1: U1001.C14 U4102.N10 | length 266.3
  Inner Layer 2 w3: v1(769.29,3900.58) 769.67,3900.2 771.58,3902.11 920.83,3902.11 948.45,3874.49 977.21,3874.49 987.83,3885.11 1003.11,3885.11 v4(1014.23,3873.99)
DQM2: U1001.D7 U4102.W10 | length 331.5
  Inner Layer 2 w3: v1(769.29,3782.47) 769.29,3744.89 786.08,3728.11 863.08,3728.11 907.85,3772.88 986.6,3772.88 991.33,3777.61 1016.12,3777.61 v4(1029.98,3763.76)
DQM3: U1001.C19 U4102.J10 | length 251.2
  Inner Layer 2 w3: v1(769.29,3979.32) 770.01,3978.61 880.33,3978.61 890.83,3968.11 938.83,3968.11 950.83,3956.11 v4@1010.85,3956.11
  other v4: 1014.23,3952.73
DQS0_C: U1001.F15 U4102.R9 | length 400.3
  Inner Layer 2 w3: v3(735.08,3854.11) 742.51,3854.11 v1(749.61,3861.21) ; v4@1061.47,3889.74 1069.08,3882.13 v3(1069.08,3871.11)
  Inner Layer 4 w3: v3(735.08,3854.11) 745.46,3843.73 996.06,3843.73 1037.19,3884.86 1055.33,3884.86 v3(1069.08,3871.11)
  other v4: 1061.47,3889.74
DQS0_T: U1001.E15 U4102.T9 | length 419
  Inner Layer 2 w3: v3(713.08,3854.11) 728.08,3839.11 747.19,3839.11 v1(749.61,3841.52) ; v4@1045.73,3889.74 1048.08,3887.38 v3(1048.08,3871.11)
  Inner Layer 4 w3: v3(713.08,3854.11) 729.46,3837.73 998.62,3837.73 1032,3871.11 v3(1048.08,3871.11)
  other v4: 1045.72,3889.74
DQS1_C: U1001.F17 U4102.N9 | length 425.2
  Top w3: v4(1061.08,3935.11) 1061.4,3923.65 1061.4,3921.3 U1001.F17@1061.47,3921.24
  Inner Layer 2 w3: v3(733.8,3910.68) 739.51,3910.68 v1(749.61,3900.58) ; v4(1061.08,3935.11) 1061.08,3943.11 v3(1069.08,3951.11)
  Inner Layer 4 w3: v3(733.8,3910.68) 741.29,3903.18 819.68,3903.18 980.08,3903.19 1042.49,3965.61 1057.58,3965.61 1069.08,3954.11 v3(1069.08,3951.11)
DQS1_T: U1001.E17 U4102.M9 | length 440.2
  Top w3: U1001.E17@1045.72,3921.24 1045.72,3923.07 1045.77,3923.12 v4(1046.08,3935.11)
  Inner Layer 2 w3: v3(712.38,3910.3) 726.26,3924.18 745.7,3924.18 v1(749.61,3920.26) ; v4(1046.08,3935.11) 1046.08,3950.11 v3(1048.08,3952.11)
  Inner Layer 4 w3: v3(712.38,3910.3) 725.5,3897.18 982.74,3897.18 1037.67,3952.11 v3(1048.08,3952.11)
DQS2_C: U1001.F12 U4102.W9 | length 406.7
  Inner Layer 2 w3: v3(733.08,3782.11) 733.44,3782.47 v1(749.61,3782.47) ; v4(1061.47,3842.5) 1061.47,3835.53 v3(1069.1,3827.91)
  Inner Layer 4 w3: v3(733.08,3782.11) 741.25,3773.94 875.77,3773.94 908.41,3806.59 1001.9,3806.59 1035.94,3840.63 1054.45,3840.63 1067.17,3827.91 v3(1069.1,3827.91)
DQS2_T: U1001.E12 U4102.Y9 | length 372.8
  Inner Layer 2 w3: v3(734.71,3760.81) 747.63,3760.81 v1(749.61,3762.78) ; v4(1045.72,3842.5) 1047.99,3840.23 v3(1047.99,3827.13)
  Inner Layer 4 w3: v3(734.71,3760.81) 741.84,3767.93 878.4,3767.93 911.04,3800.58 1004.52,3800.58 1031.07,3827.13 v3(1047.99,3827.13)
DQS3_C: U1001.E20 U4102.J9 | length 379.7
  Top w3: U1001.E20@1045.72,3968.48 1045.73,3976.11 1051.08,3981.46 v4(1051.08,3982.11)
  Inner Layer 2 w3: v3(734.08,3980.11) 734.87,3979.32 v1(749.61,3979.32) ; v3(1048.08,3997.11) 1051.08,3994.11 v4(1051.08,3982.11)
  Inner Layer 4 w3: v3(734.08,3980.11) 746.96,3967.22 1008.92,3967.22 1030.8,3989.11 1040.08,3989.11 v3(1048.08,3997.11)
DQS3_T: U1001.F20 U4102.H9 | length 458
  Top w3: U1001.F20@1061.47,3968.48 1061.47,3976.5 v4(1067.08,3982.11)
  Inner Layer 2 w3: v3(712.08,3980.11) 712.08,3982.11 725.08,3995.11 745.71,3995.11 v1(749.61,3999) ; v4(1067.08,3982.11) 1067.08,3995.11 v3(1069.08,3997.11)
  Inner Layer 4 w3: v3(712.08,3980.11) 730.96,3961.22 1011.41,3961.22 1033.29,3983.11 1055.08,3983.11 v3(1069.08,3997.11)
DSI_TE: CON6102.10 U1001.AA5 | length 2175.3
  Top w4: CON6102.10@582.62,2376.49 597.91,2376.49 608.36,2376.49 v1(614.31,2376.09) ; v4(1297.69,3732.26) U1001.AA5@1297.92,3732.49
  Inner Layer 2 w3: v4(1297.69,3732.26) 1292.95,3727.49 1292.95,3713.49 1298.95,3707.49 1298.95,3686.95 1306.64,3679.25
  Inner Layer 2 w4: v1(614.31,2376.09) 629.29,2391.07 629.29,2567.04 662.35,2600.09 742.43,2600.09 v3(742.43,2598.24) ; v3(986.94,2810.09) 1003.94,2793.09 1300.41,2793.09 1377.31,2869.99 1377.31,2974.4 1354.31,2997.4 1354.31,3000.92 1337.92,3017.31 v3(1316.54,3017.31) ; 1306.64,3679.25 1314.95,3670.95 1314.95,3637.64 1353.95,3598.64 1353.95,3375.64 1319.14,3340.83 ; v3(1309.31,3311.09) 1309.31,3331.06 1319.09,3340.83
  Inner Layer 4 w4: v3(742.43,2598.24) 743.31,2598.24 743.31,2609.33 747.11,2613.13 747.11,2627.3 739.65,2634.76 739.65,2734.65 815.08,2810.09 v3(986.94,2810.09)
  Inner Layer 5 w4: v3(1309.31,3311.09) 1298.31,3300.09 1298.31,3261.61 1313.31,3246.61 1313.31,3184.09 1302.31,3173.09 1302.31,3082.09 1308.31,3076.09 1308.31,3024.31 1315.31,3017.31 v3(1316.54,3017.31)
DVDD12_EMI: C1101.1 C4103.1 C4104.1 C4105.1 C4106.1 C4107.1 C4108.1 C10072.1 C10073.1 C10075.1 C10076.1 C10077.1 C10086.1 C10087.1 R1005.2 R1021.2 R1105.1 U1001.G9 U1001.G12 U1001.G14 U1001.G16 U1001.G18 U1001.H9 U1001.H12 U1001.H14 U1001.H16 U1001.H18 U4102.AA9 U4102.AB5 U4102.AB8 U4102.F5 U4102.F8 U4102.G9 U4102.H8 U4102.H12 U4102.J5 U4102.J11 U4102.K2 U4102.K5 U4102.K10 U4102.K12 U4102.L2 U4102.L5 U4102.L8 U4102.L9 U4102.M5 U4102.M10 U4102.M12 U4102.N2 U4102.N5 U4102.N11 U4102.P5 U4102.P8 U4102.P11 U4102.R5 U4102.R11 U4102.T5 U4102.T10 U4102.T12 U4102.U2 U4102.U5 U4102.U8 U4102.U9 U4102.V2 U4102.V5 U4102.V10 U4102.V12 U4102.W5 U4102.W11 U4102.Y8 U4102.Y12 | length 3494.8
  Top w3: R1105.1@468.81,3707.22 469.95,3708.36 R1105.1@470.13,3708.54 ; C4107.1@468.95,4077.49 468.95,4078.79 471.47,4078.79 471.47,4077.09 v1(471.47,4076.98) ; C4103.1@607.08,4225.33 C4103.1@607.08,4225.33 C4103.1@612.71,4225.33 ; v1(607.14,4230.9) C4103.1@612.71,4225.33 ; v1(621.15,4229.99) 619.34,4229.99 614.67,4225.33 C4103.1@612.71,4225.33 ; v1(649.34,4217.97) 650.03,4218.66 C4105.1@650.72,4218.66
  Top w4: 469.95,3700 470.13,3700.18 R1105.1@470.13,3708.54 470.31,3708.54 470.31,3691.19 v1(470.31,3691.09) ; v1(471.47,4076.98) 471.58,4077.09 v1(488.19,4077.09) ; v1(636.95,4217.49) 650.72,4217.49 C4105.1@650.72,4218.66 ; 718.65,3939.95 v1(729.92,3939.95) ; 762.65,3926.91 U4102.M10@769.3,3920.27 ; U4102.P11@788.98,3880.9 788.98,3889.09 ; U4102.J11@788.98,3979.32 U4102.J11@789.65,3979.99 ; v4(1092.97,3842.5) 1096.4,3842.5 1099.49,3845.59
  Top w5: 1103.98,3850.08 1104.47,3850.56 1104.47,3874.09 ; 1103.98,3910.49 1104.47,3910 1104.47,3874.09 ; v4(1092.97,3873.99) 1104.47,3874.09 ; v4(1092.97,3873.99) 1092.97,3874.09 v4(1092.97,3873.99)
  Top w6: v4(1092.97,3842.5) U1001.H12@1096.4,3842.5 ; U1001.H16@1092.97,3905.49 1103.47,3905.49 1103.98,3906 1103.98,3910.49 1103.98,3925.97 v4(1092.97,3936.99) ; 1099.49,3845.59 1103.98,3850.08
  Top w8: v1(598.08,3942.11) v1@598.08,3939.95 ; v1(611.81,3802.15) U4102.U2@611.82,3821.84 ; U4102.N2@611.82,3900.58 605.08,3900.58 598.08,3907.58 v1@598.08,3939.95 ; U4102.K2@611.82,3959.64 U4102.L2@611.82,3939.95 v1@598.08,3939.95 ; v1(670.87,3723.41) v1(729.92,3723.41) U4102.AA9@749.61,3743.1 U4102.Y8@729.93,3762.79 692.95,3763.11 673.95,3782.47 v1(670.87,3782.47) U4102.V5@670.87,3802.16 v1(670.87,3821.84) ; v1(670.87,4038.37) v1(729.92,4038.37) U4102.G9@749.61,4018.69 U4102.H8@729.93,3999.01 729.82,3999.11 690.65,3999.11 v1(670.87,3979.32) v1(670.87,3959.63) U4102.L5@670.87,3939.95 ; U4102.P8@729.93,3880.9 729.92,3881.11 U4102.P5@670.87,3881.11 ; U4102.M10@769.3,3920.27 U4102.N11@788.98,3900.58 ; U4102.P11@788.98,3880.9 U4102.R11@788.98,3861.21 ; 788.98,3889.09 U4102.N11@788.98,3900.58 ; U4102.Y12@808.67,3762.79 U4102.W11@788.98,3782.47 ; U4102.V12@808.67,3802.16 U4102.W11@788.98,3782.47 ; U4102.T12@808.67,3841.53 U4102.R11@788.98,3861.21 ; U4102.M12@808.67,3920.27 U4102.N11@788.98,3900.58 ; U4102.K12@808.67,3959.64 U4102.J11@788.98,3979.32 ; U4102.H12@808.67,3999.01 U4102.J11@788.98,3979.32 ; U1001.G9@1077.22,3795.25 U1001.H9@1089.08,3795.25 ; U1001.G12@1077.22,3842.5 v4(1092.97,3842.5) ; U1001.G14@1077.22,3873.99 1085.15,3873.99 ; v4(1077.22,3905.49) U1001.H16@1092.97,3905.49 ; U1001.G18@1077.22,3936.99 v4(1092.97,3936.99) ; v4(1090.08,3780.11) 1089.08,3781.11 U1001.H9@1089.08,3795.25 ; U1001.H9@1092.97,3795.25 U1001.H9@1089.08,3795.25 ; v1(670.87,3821.84) v1(670.87,3841.52) U4102.R5@670.87,3861.21 v1(670.87,3880.89) U4102.P5@670.87,3881.11 ; v1(670.87,3821.84) v1(729.92,3821.84) ; U4102.P5@670.87,3881.11 v1(670.87,3900.58) v1(670.87,3920.26) U4102.L5@670.87,3939.95 ; U4102.L5@670.87,3939.95 718.65,3939.95 v1(729.92,3939.95) v1(749.61,3939.95) ; v1(729.92,3821.84) 736.69,3821.84 ; v1(729.92,3821.84) 736.69,3821.84 ; 736.69,3821.84 U4102.U9@749.61,3821.84 ; U4102.U9@749.61,3821.84 U4102.T10@769.3,3841.53 U4102.R11@788.98,3861.21 ; U4102.U9@749.61,3821.84 U4102.V10@769.3,3802.16 U4102.W11@788.98,3782.47 ; v1(749.61,3939.95) 762.65,3926.91 U4102.N11@788.98,3900.58 ; v1(749.61,3939.95) U4102.K10@769.3,3959.64 U4102.J11@788.98,3979.32 ; 1085.15,3873.99 v4(1092.97,3873.99) 1085.16,3873.99
  Top w12: C1101.1@447.81,3708.33 447.81,3708.54 R1105.1@470.13,3708.54 ; v1(465.95,3930.49) v1(479.95,3930.49) ; C4107.1@468.95,4077.49 468.95,4077.09 471.47,4077.09 471.58,4077.09 485.35,4077.09 486.77,4075.67 v1(488.19,4077.09) ; C10086.1@469.95,3685.49 C10086.1@469.95,3690.72 ; R1105.1@469.95,3708.36 469.95,3700 C10086.1@469.95,3691.19 ; C10086.1@470.48,3690.92 v1(470.31,3691.09) ; v1(485.42,3691.19) 470.31,3691.19 C10086.1@469.95,3691.19 ; v1(589.89,3623.95) 589.89,3623.49 C4106.1@603.95,3623.49 v1(604.13,3623.37) ; v1(636.95,4217.49) 636.95,4218.66 C4105.1@650.03,4218.66 ; C10086.1@469.95,3690.73 v1(470.31,3691.09) ; C10086.1@469.95,3690.72 v1(470.31,3691.09) ; C10086.1@469.95,3690.73 C10086.1@469.95,3691.19
  Inner Layer 2 w4: v1(488.19,4077.09) 488.19,4077.79 504.25,4077.79 504.95,4077.79 v3(504.95,4078.49)
  Inner Layer 2 w6: v4(1077.22,3905.49) 1077.22,3886.97 v4(1092.97,3873.99)
  Inner Layer 2 w8: v3(585.08,3933.11) 594.08,3942.11 v1(598.08,3942.11) ; v3(598.17,3795.83) 604.5,3802.15 v1(611.81,3802.15) ; v3(655.84,3881.09) 655.19,3881 669.97,3881 670.08,3880.89 v1(670.87,3880.89) v1(670.87,3900.58) ; v3(669.08,3803.11) 670.08,3802.11 v3@670.87,3802.11 ; v1(670.87,3782.47) v3@670.87,3802.11 ; v1(670.87,3841.52) 670.87,3861.89 v3(671.08,3862.11) ; v1(670.87,3920.26) 670.87,3937.89 v3(672.08,3939.11) v3(693.08,3939.11) ; v1(670.87,3959.63) v1(670.87,3979.32) 670.87,3995.89 v3(671.08,3996.11) ; v1(670.87,4038.37) 685.81,4038.37 v3(686.08,4038.11) ; 703.91,3838.45 716.95,3825.41 716.95,3821.84 ; v3(714.08,3939.11) 714.92,3939.95 v1(729.92,3939.95) v1(749.61,3939.95) ; v3(714.61,4038.31) v1(729.92,4038.37) ; v3(747.08,3822.11) 746.81,3821.84 v1(729.92,3821.84) 716.95,3821.84 ; v4(1077.22,3905.49) 1089.46,3905.49 v3(1092.08,3908.11) ; v4(1090.08,3780.11) v3(1091.06,3795.13) ; v3(1090.08,3952.11) 1092.97,3949.22 v4(1092.97,3936.99) ; v3(1091.95,3826.83) v3(1091.95,3826.83) 1091.86,3827.54 v4(1092.97,3842.5) ; v3@670.87,3802.11 v1(670.87,3821.84) 716.95,3821.84
  Inner Layer 2 w10: v4(1092.97,3873.99) v3(1107.99,3873.9)
  Inner Layer 2 w12: v1(465.95,3930.49) v1(479.95,3930.49) 486.95,3923.49 v3(486.95,3914.49) ; v1(470.31,3691.09) 470.31,3691.25 470.56,3691.5 477.6,3691.5 478.1,3691 485.23,3691 v1(485.42,3691.19) 485.61,3691 485.7,3691.09 505.19,3691.09 v3(506.26,3690.03) ; v1(471.47,4076.98) 503.44,4076.98 504.25,4077.79 v3(504.95,4078.49) ; v3(575.04,3626.59) 575.04,3625.27 589.89,3625.27 v1(589.89,3623.95) 589.89,3623.66 604.13,3623.66 v1(604.13,3623.37) ; v1(607.14,4230.9) 607.14,4218.9 v3(603.07,4214.83) 603.07,4214.66 621.95,4214.66 v3(621.95,4214.49) ; v1(621.15,4229.99) 621.15,4217.99 623.3,4215.84 v3(621.95,4214.49) ; v1(649.34,4217.97) 645.31,4214.49 v3(621.95,4214.49)
  Inner Layer 5 w4: v2(1085.29,3849.29) 1085.29,3867.49 v2(1088.95,3867.49) ; v2(1086.5,3811.93) 1092.16,3806.27 1092.16,3795.13 v3(1091.06,3795.13)
  Inner Layer 5 w10: 573.97,3804.68 573.97,3849.45 605.61,3881.09 v3(655.84,3881.09) ; v3(598.17,3795.83) 603.39,3801.05 636.34,3801.05 639.78,3804.49 641.39,3804.49 642,3805.11 642.92,3805.11 643.54,3805.73 645.11,3805.73 645.51,3806.12 666.07,3806.12 v3(669.08,3803.11)
  Inner Layer 5 w12: v3(506.26,3690.03) 515.5,3690.03 531.31,3705.84 531.31,3737.37 531.02,3737.66 529.16,3737.66 518.89,3747.93 518.89,3774.7 548.87,3804.68 573.97,3804.68 589.33,3804.68 v3(598.17,3795.83) ; v2(1083.95,3772.49) 1091.06,3779.6 v3(1091.06,3795.13) ; v2(1085.95,3935.49) 1090.95,3940.49 v3@1090.95,3951.49 ; v2(1088.95,3867.49) 1095.95,3874.49 ; v3(1090.08,3952.11) v3@1090.95,3951.49 ; v2(1090.95,3978.49) v3@1090.95,3951.49 ; v3@1107.95,3874.49 v3(1107.99,3873.9)
  Inner Layer 5 w15: v3(575.04,3626.59) 575.04,3772.7 v3(598.17,3795.83) ; 1095.95,3874.49 v3@1107.95,3874.49
  Bottom w4: C10072.1@1084.95,3865.49 1084.95,3867.49 1084.95,3871.49 1084.95,3873.15
  Bottom w12: v2(1083.95,3772.49) 1083.95,3801.49 C10075.1@1084.95,3801.49 ; C10072.1@1084.95,3865.49 1084.95,3849.29 C10077.1@1084.95,3827.49 C10075.1@1084.95,3801.49 ; v2@1084.95,3871.49 v2(1088.95,3867.49) ; 1084.95,3873.15 v2(1084.95,3893.49) C10073.1@1084.95,3905.49 v2(1084.95,3922.49) 1084.95,3934.49 v2(1085.95,3935.49) 1085.95,3973.49 C10087.1@1087.95,3973.49 ; C10075.1@1085.95,3801.49 C10075.1@1084.95,3801.49
  other v1: 819.55,3624.17 831.7,3624.27 843.88,3624.19 856.37,3624 794.77,3624.63 807.45,3624.71 690.95,3793.49 690.95,3821.49 690.95,3847.49 690.95,3875.49 690.95,3899.49 690.95,3921.49 690.95,3957.49
  other v3: 872.93,3626.32 891.06,3626.45 909.31,3627.09 699.08,3715.11
DVDD18_CONN: C10082.1 R1008.1 U1001.C28 | length 280.6
  Top w12: R1008.1@792.31,4209.09 793.31,4209.09 793.31,4208.09 C10082.1@825.31,4208.09 825.31,4196.09 834.31,4187.09 873.95,4187.09 v1(881.81,4179.23)
  Inner Layer 2 w8: v1(881.81,4179.23) 886.61,4179.25 897.95,4167.91 897.95,4161.83 962.69,4097.09 1002.04,4097.09 1004.67,4094.46 v4(1014.23,4094.47)
DVDD18_EMI: C4101.1 C4102.1 SH4101.2 U4102.AA3 U4102.AA5 U4102.AB3 U4102.AB4 U4102.AB9 U4102.F3 U4102.F4 U4102.F9 U4102.G5 | length 1210.5
  Top w3: C4101.1@469.95,4023.49 C4101.1@470.95,4021.49
  Top w8: 629.56,4056.11 631.5,4054.17 ; U4102.AA3@631.5,3743.1 U4102.AB3@631.5,3723.42 ; 636.56,3703.11 631.5,3708.17 U4102.AB3@631.5,3723.42 ; 651.18,3703.11 U4102.AB4@651.19,3723.42 ; U4102.AA5@670.87,3743.1 U4102.AB4@651.19,3723.42 ; U4102.G5@670.87,4018.69 U4102.F4@651.19,4038.38 ; 733.11,4056.11 749.61,4039.61 U4102.F9@749.61,4038.38 ; 736.74,3703.11 749.61,3715.97 U4102.AB9@749.61,3723.42 ; U4102.AB3@631.5,3723.42 U4102.AB4@651.19,3723.42 ; U4102.F3@631.5,4038.38 631.5,4054.17 ; U4102.F3@631.5,4038.38 U4102.F4@651.19,4038.38 ; U4102.F3@631.5,4038.38 631.5,4054.17 ; U4102.F4@651.19,4038.38 651.18,4056.11 U4102.F4@651.19,4038.38
  Top w15: SH4101.2@464.95,3993.49 464.95,4018.49 469.95,4023.49 C4102.1@469.95,4053.49 472.63,4056.16 v1@507.43,4056.16 ; v1(507.13,4056.09) v1@507.43,4056.16 ; v1@507.47,4056.17 v1@509.31,4056.16 ; v1@519.32,4056.25 519.32,4056.16 629.56,4056.16 629.56,4056.11 651.18,4056.11 733.11,4056.11 ; v1(519.36,4056.25) 519.32,4056.44 v1@509.31,4056.16 ; v1@507.43,4056.16 v1@509.31,4056.16
  Top w20: v1(609.08,3703.11) v1(621.53,3703.11) 636.56,3703.11 651.18,3703.11 736.74,3703.11
  Inner Layer 2 w4: v1(507.13,4056.09) v1@507.21,4056.17 ; v1@507.23,4056.17 v1@510.81,4052.59
  Inner Layer 2 w12: v1(507.13,4056.09) 507.13,4056.17 v1@507.21,4056.17 ; v1@507.23,4056.17 519.36,4056.17 v1(519.36,4056.25) ; v1(609.08,3703.11) v1(621.53,3703.11)
  Inner Layer 2 w15: v3(596.08,3710.86) 603.83,3703.11 v1(609.08,3703.11)
  Inner Layer 2 w20: v3(510.81,3714.33) 514.45,3717.97 514.45,4048.95 v1@510.81,4052.59
  Inner Layer 4 w18: v3(510.81,3714.33) 514.28,3710.86 v3(596.08,3710.86)
DVDD18_IO: C10084.1 C10085.1 C10096.1 C10097.1 R1012.1 U1001.AA29 U1001.AB29 U1001.AD3 U1001.AL20 U1001.AL26 U1001.K27 | length 3335.3
  Top w4: v4(1124.46,4078.72) 1124.72,4078.71 v4(1124.46,4078.72) ; v1(1227.95,4281.83) 1228.95,4282.83 R1012.1@1231.95,4282.83 ; 1563.31,4014.5 1564.95,4016.14 C10097.1@1564.95,4024.49
  Top w8: v4(1297.69,4110.21) U1001.AB29@1313.44,4110.21 ; U1001.AL20@1455.17,3968.48 1456.56,3968.48 1461.03,3972.95 1466.2,3978.12 1530.6,3978.12 1550.58,3998.09 C10085.1@1563.31,3998.09 ; U1001.AL26@1455.17,4062.97 1467.18,4062.97 1487.53,4083.32 1487.66,4083.32 1497.31,4092.97 v1(1499.32,4092.97)
  Top w10: C10084.1@1304.95,4260.49 1306.95,4258.49 v1(1306.95,4204.83) ; 1558.31,4293.49 1592.31,4293.49 1603.46,4282.34 1603.46,4132 1603.09,4131.63 1603.09,4118.26 v1@1602.93,4118.26 ; C10097.1@1564.95,4024.49 1564.95,4030.72 1566.31,4032.09 1567.53,4032.09 1602.93,4067.48 v1@1602.93,4118.26 ; v1(1602.57,4119.31) 1602.93,4118.95 v1@1602.93,4118.26
  Top w12: R1012.1@1231.95,4282.83 1232.95,4282.83 1232.95,4286.49 1266.85,4286.49 1292.85,4260.49 C10084.1@1304.95,4260.49 1311.25,4260.49 1344.25,4293.49 1558.31,4293.49 ; v1(1467,3513.05) 1518.44,3513.05 1531,3500.49 v1(1589.95,3500.49) ; C10085.1@1563.31,3998.09 1563.31,4014.5 1563.31,4022.85 C10097.1@1564.95,4024.49
  Inner Layer 2 w8: v4(1124.46,4078.72) 1154.85,4048.32 v3(1154.85,4033.2) ; v4(1344.94,3700.77) 1344.93,3690.6 1351.31,3684.22 1351.31,3673.62 1450.31,3574.62 1450.31,3529.74 v1(1467,3513.05)
  Inner Layer 2 w10: v3(1215.18,4364.56) 1204.31,4353.7 1204.31,4305.47 v1(1227.95,4281.83) ; v4(1297.69,4110.21) 1305.95,4118.47 1305.95,4203.83 v1(1306.95,4204.83) ; v1(1499.32,4092.97) 1499.32,4093.5 1510.32,4093.5 1523.36,4106.53 1589.79,4106.53 v1(1602.57,4119.31) 1614.12,4130.86 1614.12,4159.45 1646.04,4191.38 1646.95,4191.38 1698.44,4242.87 1833.67,4242.87 v3(1847.95,4257.15) ; v1(1589.95,3500.49) 1601.24,3500.49 1608.34,3493.39 v3(1623.97,3493.39)
  Inner Layer 4 w8: v3(1154.85,4033.2) 1152.31,4035.73 1152.31,4099.58 1137.31,4114.58 1137.31,4279.01 1195.15,4336.84 1195.15,4344.53 v3(1215.18,4364.56)
  Inner Layer 5 w10: v3(1623.97,3493.39) 1623.97,3545.21 1669.95,3591.19 1669.95,3759.39 v2(1681.65,3771.09)
  Inner Layer 5 w12: v3(1215.18,4364.56) 1215.63,4364.11 1231.33,4379.8 v2(1231.78,4379.35) ; v2(1741.65,3992.09) 1756.02,3992.09 1765.15,4001.22 1765.15,4046.59 1764.65,4047.09 1764.65,4103.59 1781.65,4120.59 1781.65,4158.19 1778.57,4161.28 1778.57,4205.1 1830.62,4257.15 v3(1847.95,4257.15)
  Bottom w4: v2(1231.78,4379.35) C10096.1@1231.95,4379.49
  Bottom w12: v2(1681.65,3771.09) 1726.65,3816.09 1726.65,3872.14 1741.65,3887.14 v2(1741.65,3992.09)
DVDD18_MIPIRX: C10093.1 R1026.1 U1001.N30 U1001.W31 | length 377.3
  Top w8: R1026.1@1166.95,4248.49 R1026.1@1166.95,4247.49 ; U1001.N30@1171.71,4125.96 1171.71,4153.97 1171.95,4154.22 1164.08,4162.09 1164.08,4247.49 R1026.1@1166.95,4247.49 ; U1001.W31@1266.2,4141.71 1266.19,4145.07 1272.95,4151.83 1272.95,4168.83 1278.95,4174.83 C10093.1@1278.95,4193.83 1280.78,4193.83 1280.78,4192 1292.95,4204.17 1292.95,4224.6 1252.72,4264.83 1184.29,4264.83 R1026.1@1166.95,4247.49
DVDD18_MIPITX: C10094.1 R1028.1 U1001.T1 | length 146.5
  Top w4: C10094.1@1202.95,3584.49 C10094.1@1203.95,3585.49
  Top w8: R1028.1@1192.95,3533.49 1192.95,3550.49 1200.95,3558.49 1200.95,3582.49 C10094.1@1202.95,3584.49 ; C10094.1@1203.95,3585.49 1203.95,3636.49 1218.95,3651.49 U1001.T1@1218.95,3669.27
